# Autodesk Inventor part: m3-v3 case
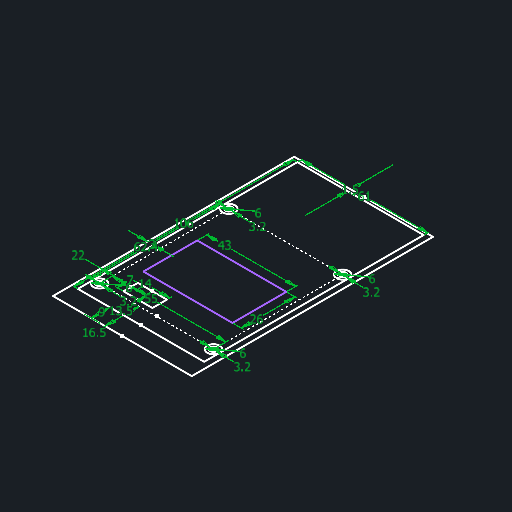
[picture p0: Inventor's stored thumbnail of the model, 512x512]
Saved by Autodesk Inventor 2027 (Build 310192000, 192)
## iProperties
Created: 2026-10
Part Number: m3-v3 case
Material: 일반
Document SubType Name: Modeling
Designer: khw
Density: 1 g/cm^3
Appearance: 기본값
Author: khw
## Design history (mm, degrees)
sketch "스케치1"
  geometry: L1 (0, 0)-(61, 0); L2 (61, 0)-(61, -106); L3 (61, -106)-(0, -106); L4 (0, -106)-(0, 0); L5 (64, 9)-(-3, 9); L6 (-3, 9)-(-3, -107.5); L7 (-3, -107.5)-(64, -107.5); L8 (64, -107.5)-(64, 9); L9 (49, -10)-(35, -10); L10 (35, -10)-(35, -17); L11 (35, -17)-(49, -17); L12 (49, -17)-(49, -10); L13 (58, -7.5)-(3, -7.5); L14 (3, -7.5)-(3, -69.9); L15 (3, -69.9)-(58, -69.9); L16 (58, -69.9)-(58, -7.5); L17 (52.411, -23.072)-(9.411, -23.072); L18 (9.411, -23.072)-(9.411, -49.072); L19 (9.411, -49.072)-(52.411, -49.072); L20 (52.411, -49.072)-(52.411, -23.072); C1 r 1.6 at (58, -7.5); C2 r 3 at (58, -7.5); C3 r 1.6 at (3, -7.5); C4 r 3 at (3, -7.5); C5 r 1.6 at (3, -69.9); C6 r 3 at (3, -69.9); C7 r 1.6 at (58, -69.9); C8 r 3 at (58, -69.9); 6 further points
  constraints: 40 end point, 10 parallel, 8 centre point, 8 coincident, 6 midpoint, 5 horizontal, 5 perpendicular, 2 vertical alignment
  dimensions: "d0" = 61 distance of L2.end L3.end; "d1" = 106 distance of L1.end L2.end; "d2" = 9 distance between parallel lines of L1 L5; "d3" = 1.5 distance between parallel lines of L7 L3; "d4" = 3 distance between parallel lines of L2 L8; "d6" = 13.5 distance from line of L1 point (49, -13.5); "d8" = 7 distance of L11.end L9.start; "d9" = 14 distance of L10.end L11.end; "d11" = 62.4 distance of L15.end L13.start; "d12" = 55 distance of L13.start L13.end; "d13" = 3.2 diameter of C1; "d14" = 6 diameter of C2; "d15" = 3.2 diameter of C3; "d16" = 6 diameter of C4; "d17" = 3.2 diameter of C5; "d18" = 6 diameter of C6; "d19" = 3.2 diameter of C7; "d20" = 6 diameter of C8; "d21" = 16.5 distance between parallel lines of L5 L13; "d22" = 26 distance of L17.end L18.end; "d23" = 43 distance of L18.end L19.end; "d24" = 22 distance from line of L8 point (42, -17)
